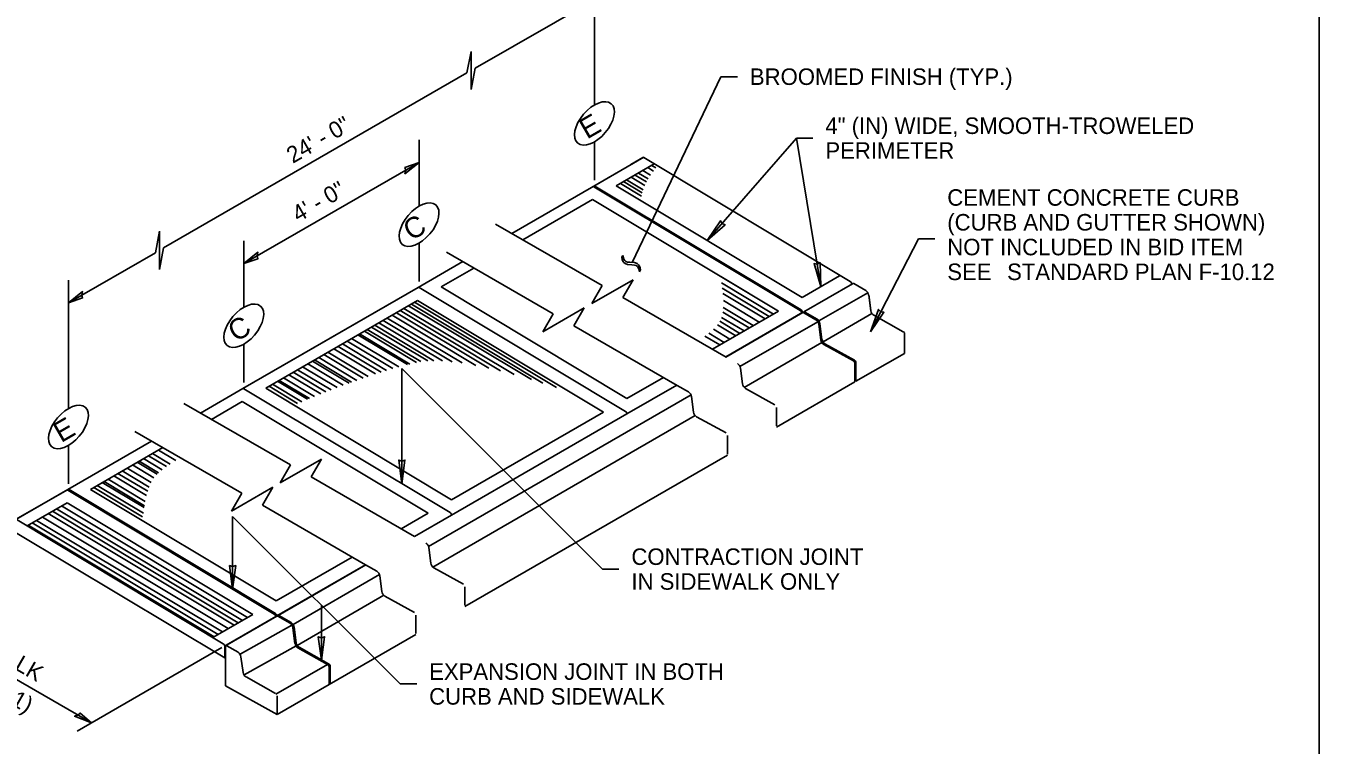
# Model space of a CAD drawing. Extents: x 99862 to 103151, y 100000 to 102076.
# Drawn here: x 101899 to 103151, y 100659 to 101355 of the extents above; entities that cross this region are included whole.
import ezdxf

# ---------------------------------------------------------------- set-up
doc = ezdxf.new("R2010")
doc.units = 0
for name, color, linetype in [('Level 1', 7, 'Continuous'), ('Level 15', 7, 'Continuous'), ('Level 20', 7, 'Continuous'), ('Level 27', 7, 'Continuous'), ('Level 30', 7, 'Continuous'), ('Level 4', 7, 'Continuous'), ('Level 7', 7, 'Continuous')]:
    doc.layers.add(name, color=color, linetype=linetype)

msp = doc.modelspace()

# ---------------------------------------------------------------- linework, layer by layer
at = {"layer": 'Level 1'}
msp.add_lwpolyline([(99862, 99999.5), (103151, 99999.5), (103151, 102075.5), (99862, 102075.5)], close=True, dxfattribs=at)
at = {"layer": 'Level 15'}
for p, q in [((102449.4, 101278.5), (102449.4, 101402.9)), ((102334, 101314.3), (102449.4, 101380.9)), ((102330, 101330.5), (102326, 101309.7)), ((102330, 101293.5), (102330, 101330.5)), ((102032.3, 101140.1), (102326, 101309.7)), ((102330, 101293.5), (102334, 101314.3)), ((102485.9, 101126.1), (102571.9, 101306)), ((102571.9, 101306), (102587.9, 101306)), ((102279.6, 101180.5), (102279.6, 101244.9)), ((102449.4, 101205.7), (102449.4, 101242.8)), ((102558.7, 101147.3), (102644.9, 101246.5)), ((102668.7, 101102.9), (102644.9, 101246.5)), ((102644.9, 101246.5), (102660.9, 101246.5)), ((102109.9, 101125), (102279.6, 101222.9)), ((102028.3, 101156.3), (102024.3, 101135.5)), ((102028.3, 101119.3), (102028.3, 101156.3)), ((102457, 101103.6), (102353.7, 101163.2)), ((102109.9, 101082.6), (102109.9, 101147)), ((102279.6, 101107.7), (102279.6, 101144.8)), ((102716.6, 101059), (102763, 101149)), ((102763, 101149), (102779, 101149)), ((101940.2, 101087), (102024.3, 101135.5)), ((102028.3, 101119.3), (102032.3, 101140.1)), ((102306.3, 101135.9), (102409.6, 101076.3)), ((101940.2, 100984.6), (101940.2, 101109)), ((102487, 101109.4), (102447, 101086.3)), ((102447, 101086.3), (102457, 101103.6)), ((102477, 101092.1), (102487, 101109.4)), ((102576.9, 101034.4), (102477, 101092.1)), ((102399.6, 101058.9), (102439.6, 101082)), ((102439.6, 101082), (102429.6, 101064.7)), ((102409.6, 101076.3), (102399.6, 101058.9)), ((102429.6, 101064.7), (102529.6, 101007)), ((102109.9, 101009.7), (102109.9, 101046.8)), ((102457.1, 100829.1), (102262.9, 101023.3)), ((102262.9, 100911.8), (102262.9, 101023.3)), ((102592.7, 101008.4), (102590.7, 101023.7)), ((102529.6, 101007), (102540.6, 101000.7)), ((102624.2, 100988.2), (102595.6, 101004.1)), ((102543.4, 100996.4), (102545.4, 100981.1)), ((102155.3, 100929.9), (102052, 100989.5)), ((102625.7, 100967.8), (102625.7, 100985.7)), ((102548.2, 100976.7), (102576.9, 100960.9)), ((102004.6, 100962.2), (102107.9, 100902.5)), ((102578.3, 100958.4), (102578.3, 100940.5)), ((101940.2, 100911.8), (101940.2, 100948.9)), ((102185.3, 100935.6), (102145.3, 100912.6)), ((102145.3, 100912.6), (102155.3, 100929.9)), ((102175.3, 100918.3), (102185.3, 100935.6)), ((102275.2, 100860.6), (102175.3, 100918.3)), ((102097.9, 100885.2), (102137.9, 100908.3)), ((102107.9, 100902.5), (102097.9, 100885.2)), ((102137.9, 100908.3), (102127.9, 100891)), ((102127.9, 100891), (102227.8, 100833.3)), ((102261.4, 100717.8), (102099.1, 100880.1)), ((102099.1, 100880.1), (102099.1, 100809.7)), ((102291, 100834.7), (102289, 100850)), ((102227.8, 100833.3), (102238.8, 100827)), ((102322.5, 100814.5), (102293.9, 100830.3)), ((102457.1, 100829.1), (102473.1, 100829.1)), ((102241.6, 100822.6), (102243.7, 100807.4)), ((102246.5, 100803), (102275.2, 100787.1)), ((102324, 100794.1), (102324, 100812)), ((101755.5, 100799.6), (101962.4, 100680.2)), ((102185.1, 100740.8), (102185.1, 100794.1)), ((102276.6, 100784.6), (102276.6, 100766.7)), ((101948.7, 100672.1), (102088.7, 100753.1)), ((102261.4, 100717.8), (102277.4, 100717.8))]:
    msp.add_line(p, q, dxfattribs=at)
for points in [[(102279.6, 101222.9), (102266, 101212), (102266.7, 101215.4), (102266, 101218.2)], [(102558.7, 101147.3), (102575.9, 101162.6), (102573, 101163.7), (102571.4, 101166.5)], [(102109.9, 101125), (102123.6, 101135.9), (102122.9, 101132.5), (102123.6, 101129.7)], [(102668.7, 101102.9), (102662, 101124.9), (102665.1, 101124.3), (102667.9, 101125.9)], [(101940.2, 101087), (101953.9, 101097.9), (101953.2, 101094.5), (101953.9, 101091.8)], [(102716.6, 101059), (102724.4, 101080.6), (102726.6, 101078.3), (102729.7, 101077.9)], [(102262.9, 100911.8), (102265.9, 100934.7), (102262.9, 100933.6), (102260, 100934.7)], [(102099.1, 100809.7), (102102.1, 100832.5), (102099.1, 100831.5), (102096.2, 100832.5)], [(102185.1, 100740.8), (102188.1, 100763.6), (102185.1, 100762.6), (102182.1, 100763.6)], [(101962.4, 100680.2), (101951.5, 100689.6), (101949.4, 100687.7), (101946.1, 100686.5)]]:
    msp.add_lwpolyline(points, close=True, dxfattribs=at)
for centre, start_param, end_param in [((102587.9, 101024.8), 0.950564, 2.35604), ((102595.5, 101007.4), 4.092139, 5.517494), ((102540.6, 100997.4), 0.950564, 2.35604), ((102548.2, 100980), 4.092139, 5.517494), ((102286.2, 100851), 0.950564, 2.35604), ((102293.8, 100833.6), 4.092139, 5.517494), ((102238.8, 100823.7), 0.950564, 2.35604), ((102246.5, 100806.3), 4.092139, 5.517494)]:
    msp.add_ellipse(centre, major_axis=(2, -3.46), ratio=0.57735, start_param=start_param, end_param=end_param, dxfattribs=at)
at = {"layer": 'Level 20'}
for p, q in [((102476.9, 101132.9), (102475.9, 101131.1)), ((102475.9, 101131.1), (102476.2, 101129)), ((102476.2, 101129), (102476.9, 101127.3)), ((102477.9, 101129.4), (102476.9, 101132.9)), ((102478.8, 101128), (102477.9, 101129.4)), ((102479.9, 101127.1), (102478.8, 101128)), ((102476.9, 101127.3), (102477.8, 101126)), ((102477.8, 101126), (102479.2, 101125)), ((102479.2, 101125), (102481.5, 101124.1)), ((102481.3, 101126.5), (102479.9, 101127.1)), ((102483.7, 101126.3), (102481.3, 101126.5)), ((102481.5, 101124.1), (102485.6, 101123.9)), ((102488.1, 101125.9), (102483.7, 101126.3)), ((102485.6, 101123.9), (102488.1, 101123.6)), ((102490.7, 101125), (102488.1, 101125.9)), ((102488.1, 101123.6), (102489.9, 101123)), ((102489.9, 101123), (102491, 101122.2)), ((102492, 101123.9), (102490.7, 101125)), ((102491, 101122.2), (102491.8, 101121.1)), ((102491.8, 101121.1), (102492.4, 101119.5)), ((102493.1, 101122.6), (102492, 101123.9)), ((102492.4, 101119.5), (102492.9, 101117.1)), ((102492.9, 101117.1), (102494, 101118.9)), ((102493.7, 101120.9), (102493.1, 101122.6)), ((102494, 101118.9), (102493.7, 101120.9))]:
    msp.add_line(p, q, dxfattribs=at)
for centre in [(102449.4, 101260.7), (102279.6, 101162.7), (102109.9, 101064.7), (101940.2, 100966.7)]:
    msp.add_ellipse(centre, major_axis=(-16.2, -19.1), ratio=0.550454, dxfattribs=at)
at = {"layer": 'Level 27'}
for p, q in [((102666.8, 101069.4), (102714.2, 101096.7)), ((102590.3, 101025.2), (102665.7, 101068.7)), ((102670.7, 101049.1), (102718.1, 101076.5)), ((102594.4, 101005.1), (102669.6, 101048.5)), ((102288.7, 100851.1), (102542.9, 100997.9)), ((102292.9, 100831), (102547, 100977.7)), ((102157.6, 100775.4), (102241.4, 100823.7)), ((102161.6, 100755.2), (102245.6, 100803.7)), ((102156.6, 100774.8), (102106.3, 100746.7)), ((102160.5, 100754.6), (102110.2, 100726.5))]:
    msp.add_line(p, q, dxfattribs=at)
at = {"layer": 'Level 30'}
for p, q in [((102506.6, 101214.6), (102501.1, 101217.9)), ((102509, 101217.6), (102504.9, 101220.1)), ((102495.6, 101193.6), (102477.7, 101204.4)), ((102496.5, 101196.3), (102480.4, 101206)), ((102498.1, 101200.6), (102484.9, 101208.6)), ((102499.8, 101204.1), (102488.7, 101210.7)), ((102501.5, 101207.1), (102492.1, 101212.7)), ((102503.7, 101210.6), (102496.3, 101215.1)), ((102494.9, 101190.4), (102474.6, 101202.6)), ((102571.9, 101112.4), (102627.5, 101079)), ((102572.5, 101106.3), (102622.7, 101076.1)), ((102573.1, 101101.1), (102618.6, 101073.8)), ((102573.7, 101096), (102614.6, 101071.5)), ((102261.2, 101079.4), (102358.3, 101021.1)), ((102265, 101081.6), (102371.6, 101017.6)), ((102269.4, 101084.2), (102388.5, 101012.7)), ((102272.2, 101085.8), (102399.6, 101009.3)), ((102275.3, 101087.5), (102412.7, 101005)), ((102573.6, 101077.9), (102599.2, 101062.6)), ((102574.1, 101082.4), (102603.2, 101064.9)), ((102574.2, 101089.1), (102608.9, 101068.2)), ((102236.7, 101065.3), (102293.9, 101030.9)), ((102240.8, 101067.7), (102302.3, 101030.7)), ((102245, 101070), (102311.7, 101029.9)), ((102248.8, 101072.2), (102321.2, 101028.7)), ((102253.6, 101075), (102334.5, 101026.4)), ((102257.7, 101077.4), (102347.1, 101023.8)), ((102568.6, 101065.6), (102586.2, 101055.1)), ((102570.9, 101069.1), (102590.3, 101057.4)), ((102572.4, 101072.9), (102594.3, 101059.8)), ((102220.4, 101055.9), (102268.3, 101027.1)), ((102222.1, 101056.9), (102270.7, 101027.7)), ((102226.7, 101059.5), (102277.2, 101029.2)), ((102229.5, 101061.1), (102281.3, 101030)), ((102233.6, 101063.5), (102288.2, 101030.7)), ((102556.4, 101054.8), (102570.8, 101046.2)), ((102560, 101057.5), (102574.9, 101048.5)), ((102564.6, 101061.4), (102580.5, 101051.8)), ((102197.1, 101042.4), (102237.5, 101018.1)), ((102201.2, 101044.8), (102242.8, 101019.8)), ((102205.4, 101047.2), (102248.1, 101021.5)), ((102210, 101049.8), (102254.1, 101023.3)), ((102214.3, 101052.3), (102259.9, 101025)), ((102171.9, 101027.8), (102206.3, 101007.1)), ((102176.4, 101030.5), (102211.8, 101009.2)), ((102178.4, 101031.6), (102214.2, 101010.1)), ((102182.6, 101034), (102219.4, 101011.9)), ((102187.4, 101036.8), (102225.4, 101014)), ((102191.3, 101039.1), (102230.2, 101015.7)), ((102153.7, 101017.3), (102184.6, 100998.8)), ((102157.8, 101019.7), (102189.5, 101000.7)), ((102161.9, 101022.1), (102194.4, 101002.6)), ((102166.8, 101024.9), (102200.2, 101004.8)), ((102134.4, 101006.2), (102162, 100989.6)), ((102137.8, 101008.2), (102166, 100991.2)), ((102142.6, 101011), (102171.7, 100993.6)), ((102144.3, 101011.9), (102173.6, 100994.3)), ((102148.4, 101014.3), (102178.3, 100996.3)), ((102021.6, 100941.1), (102038.7, 100930.8)), ((102027.4, 100944.4), (102044.3, 100934.3)), ((102002.2, 100929.9), (102023, 100917.4)), ((102006.7, 100932.5), (102026, 100920.9)), ((102008.7, 100933.6), (102027.4, 100922.3)), ((102012.9, 100936.1), (102030.8, 100925.3)), ((102017.7, 100938.8), (102035.1, 100928.4)), ((101978.7, 100916.3), (102014.6, 100894.7)), ((101984, 100919.3), (102015.8, 100900.3)), ((101988.1, 100921.8), (102016.9, 100904.5)), ((101992.2, 100924.1), (102018.3, 100908.5)), ((101997.1, 100926.9), (102020.3, 100913)), ((101964.7, 100908.2), (102012, 100879.8)), ((101968.1, 100910.2), (102012.7, 100883.4)), ((101972.9, 100913), (102013.5, 100888.6)), ((101974.6, 100913.9), (102013.8, 100890.4)), ((101933.6, 100890.2), (102113.5, 100782.2)), ((101914.9, 100879.5), (102094.9, 100771.4)), ((101920.6, 100882.8), (102100.6, 100774.7)), ((101924.7, 100885.1), (102104.6, 100777)), ((101928.7, 100887.4), (102108.7, 100779.4)), ((101901.1, 100871.5), (102081.1, 100763.5)), ((101905.2, 100873.9), (102085.2, 100765.8)), ((101909.3, 100876.2), (102089.2, 100768.2))]:
    msp.add_line(p, q, dxfattribs=at)
at = {"layer": 'Level 4'}
for p, q in [((102446.6, 101198.8), (102497.1, 101228)), ((102497.1, 101228), (102448.9, 101200.1)), ((102484.5, 101221.1), (102496.1, 101227.8)), ((102497.1, 101227.6), (102696.9, 101107.7)), ((102446.6, 101198.8), (102369.3, 101154.2)), ((102369.3, 101154.2), (102446.6, 101198.8)), ((102446.6, 101198.8), (102446.6, 101198.8)), ((102648.6, 101079.4), (102448.8, 101199.4)), ((102449.9, 101200), (102649.6, 101080.1)), ((102278.6, 101101.8), (102322, 101126.9)), ((102322, 101126.9), (102278.6, 101101.8)), ((102699.3, 101105.3), (102652.2, 101078.1)), ((102698.3, 101105.1), (102699.4, 101105.7)), ((102698.3, 101105.3), (102698.3, 101105.1)), ((102698.3, 101105.1), (102698.3, 101105.1)), ((102700.4, 101105.6), (102712.1, 101098.9)), ((102278.6, 101101.8), (102108.9, 101003.9)), ((102193.6, 101052.7), (102278.6, 101101.8)), ((102279.6, 101101.7), (102479.4, 100981.8)), ((102716.9, 101079.6), (102714.9, 101094.8)), ((102714.9, 101094.5), (102714.9, 101094.5)), ((102714.9, 101094.5), (102717, 101079.3)), ((102651, 101077.8), (102576.5, 101034.7)), ((102653.2, 101078), (102664.9, 101071.2)), ((102717, 101079.3), (102717, 101079.3)), ((102651.1, 101077.5), (102576.7, 101034.5)), ((102663.8, 101070.6), (102652.1, 101077.4)), ((102668.7, 101051), (102666.6, 101066.3)), ((102667.7, 101066.9), (102669.7, 101051.6)), ((102719.8, 101074.9), (102719.8, 101074.9)), ((102719.8, 101074.9), (102748.4, 101059)), ((102108.9, 101003.9), (102193.6, 101052.7)), ((102749.5, 101058), (102749.5, 101038)), ((102700.1, 101030.8), (102671.5, 101046.6)), ((102672.6, 101047.3), (102701.2, 101031.4)), ((102701.6, 101011.6), (102701.6, 101028.3)), ((102749.5, 101038), (102702.6, 101011)), ((102702.6, 101028.9), (102702.6, 101011)), ((102068, 100980.2), (102108.9, 101003.9)), ((102309.7, 100883.8), (102109.9, 101003.7)), ((102529.1, 101007.3), (102480.8, 100979.3)), ((102701.6, 101010.4), (102625.7, 100966.7)), ((102702.6, 101011), (102701.6, 101011.6)), ((102701.6, 101010.4), (102701.6, 101011.6)), ((102480.8, 100979.3), (102311.1, 100881.4)), ((101939.7, 100906.2), (102020.7, 100952.9)), ((102578.3, 100939.4), (102324, 100793)), ((101889.2, 100877), (101939.7, 100906.2)), ((101938.7, 100905.6), (101889.7, 100877.3)), ((102139.5, 100785.5), (101939.7, 100905.5)), ((101940.8, 100906.1), (102140.5, 100786.1)), ((102311.1, 100881.4), (102275.2, 100860.6)), ((101890.4, 100876.8), (102090.1, 100756.8)), ((102091.5, 100743), (101888.9, 100864.6)), ((102227.8, 100833.3), (102141.9, 100783.7)), ((102228, 100833.2), (102143.1, 100784.2)), ((102141.9, 100783.5), (102091.5, 100754.4)), ((102140.9, 100783.1), (102092.8, 100755.3)), ((102140.9, 100782.9), (102140.9, 100783.1)), ((102141.9, 100783.7), (102141.9, 100783.5)), ((102154.7, 100776.7), (102143, 100783.5)), ((102144, 100784.1), (102155.8, 100777.3)), ((102276.6, 100765.7), (102142.2, 100688.3)), ((102159.5, 100757.1), (102157.5, 100772.3)), ((102158.6, 100772.9), (102160.6, 100757.7)), ((102091.5, 100754.4), (102091.5, 100743)), ((102092.2, 100716), (102092.2, 100754)), ((102093.4, 100754.9), (102104.4, 100748.6)), ((102191, 100736.8), (102162.4, 100752.7)), ((102163.4, 100753.3), (102192.1, 100737.4)), ((102107.2, 100744.2), (102109.2, 100729)), ((102191, 100736.8), (102141, 100707.9)), ((102192.5, 100717.3), (102192.5, 100734.4)), ((102193.5, 100735), (102193.5, 100717.9)), ((102142.2, 100688.3), (102092.2, 100716)), ((102112.1, 100724.6), (102140.7, 100708.7)), ((102193.5, 100717.9), (102192.5, 100718.5)), ((102142.2, 100706.2), (102142.2, 100688.3))]:
    msp.add_line(p, q, dxfattribs=at)
for centre, major_axis, start_param, end_param in [((102497.1, 101226), (-1, 1.73), 5.478482, 6.263654), ((102696.9, 101106.1), (-1, 1.73), 3.927706, 5.47779), ((102700.4, 101104), (-1, 1.73), 5.499053, 6.283185), ((102279.6, 101100.1), (-1, 1.73), 5.47779, 6.283214), ((102279.6, 101100.1), (1, -1.73), 2.336197, 3.141593), ((102279.6, 101100.1), (1, -1.73), 3.125285, 3.141491), ((102712.1, 101095.6), (-2, 3.46), 4.092157, 5.497787), ((102648.6, 101077.8), (-1, 1.73), 4.010451, 5.47779), ((102649.6, 101078.4), (1, -1.73), 0.869364, 2.336197), ((102652.1, 101075.8), (-1, 1.73), 5.497787, 6.283202), ((102653.2, 101076.4), (1, -1.73), 2.356194, 3.700583), ((102719.8, 101078.2), (-2, 3.46), 0.950547, 2.376192), ((102663.8, 101067.3), (-2, 3.46), 4.092157, 5.497787), ((102664.9, 101068), (2, -3.46), 0.950564, 2.356194), ((102748.5, 101057.4), (-1, 1.73), 4.727378, 5.517796), ((102671.4, 101049.9), (-2, 3.46), 0.950547, 2.376192), ((102672.5, 101050.6), (2, -3.46), 4.092139, 5.517784), ((102700.2, 101029.1), (-1, 1.73), 4.930096, 5.517796), ((102700.2, 101029.1), (-1, 1.73), 3.926984, 4.930836), ((102701.2, 101029.7), (1, -1.73), 1.787425, 2.376203), ((102701.2, 101029.7), (1, -1.73), 0.785392, 1.788296), ((102109.9, 101002.1), (-1, 1.73), 5.47779, 6.283185), ((102109.9, 101002.1), (1, -1.73), 2.336197, 3.141593), ((102109.9, 101002.1), (1, -1.73), 3.127788, 3.140446), ((102479.4, 100980.2), (-1, 1.73), 3.926981, 5.47779), ((102479.4, 100980.2), (1, -1.73), 0.785388, 2.336197), ((101939.7, 100903.8), (-1, 1.73), 5.47779, 6.283219), ((101940.7, 100904.4), (1, -1.73), 2.336197, 3.152337), ((101940.7, 100904.4), (1, -1.73), 3.140368, 3.152337), ((102309.7, 100882.2), (-1, 1.73), 3.926981, 5.47779), ((102309.7, 100882.2), (1, -1.73), 0.785388, 2.336197), ((102139.4, 100783.9), (-1, 1.73), 3.926981, 5.47779), ((102140.5, 100784.5), (1, -1.73), 0.785388, 2.336197), ((102143, 100781.8), (-1, 1.73), 5.497787, 6.283202), ((102144, 100782.4), (1, -1.73), 2.356194, 3.700583), ((102155.8, 100774), (2, -3.46), 0.950564, 2.356194), ((102154.7, 100773.4), (-2, 3.46), 4.092157, 5.497787), ((102090.1, 100755.2), (1, -1.73), 0.785388, 2.336197), ((102093.6, 100753.2), (1, -1.73), 2.356194, 3.926988), ((102162.3, 100756), (-2, 3.46), 0.950547, 2.376192), ((102163.4, 100756.6), (2, -3.46), 4.092139, 5.517784), ((102104.4, 100745.3), (2, -3.46), 0.950564, 2.35604), ((102112, 100727.9), (2, -3.46), 4.092139, 5.517494), ((102191.1, 100735.2), (-1, 1.73), 4.726483, 5.517796), ((102191.1, 100735.2), (-1, 1.73), 3.926984, 4.726483), ((102192.1, 100735.8), (1, -1.73), 1.58489, 2.376203), ((102192.1, 100735.8), (1, -1.73), 0.785392, 1.58489)]:
    msp.add_ellipse(centre, major_axis=major_axis, ratio=0.57735, start_param=start_param, end_param=end_param, dxfattribs=at)
at = {"layer": 'Level 7'}
for p, q in [((102507.3, 101221.5), (102470.6, 101200.3)), ((102470.6, 101200.3), (102650.5, 101092.2)), ((102447.6, 101187), (102380.1, 101148)), ((102627.5, 101079), (102447.6, 101187)), ((102332.7, 101120.7), (102300.9, 101102.3)), ((102650.5, 101092.2), (102686.5, 101113)), ((102300.9, 101102.3), (102480.8, 100994.2)), ((102278.2, 101089.2), (102131.2, 101004.3)), ((102458.2, 100981.2), (102278.2, 101089.2)), ((102563.6, 101042.1), (102627.5, 101079)), ((102131.2, 101004.3), (102311.1, 100896.3)), ((102480.8, 100994.2), (102516.3, 101014.7)), ((102108.5, 100991.3), (102078.7, 100974.1)), ((102288.5, 100883.2), (102108.5, 100991.3)), ((102311.1, 100896.3), (102458.2, 100981.2)), ((102031.4, 100946.7), (101961.4, 100906.3)), ((101961.4, 100906.3), (102141.4, 100798.3)), ((101938.8, 100893.3), (101900.1, 100870.9)), ((102118.8, 100785.2), (101938.8, 100893.3)), ((102262.3, 100868.1), (102288.5, 100883.2)), ((102141.4, 100798.3), (102215, 100840.7)), ((102080.1, 100762.9), (102118.8, 100785.2))]:
    msp.add_line(p, q, dxfattribs=at)

# ---------------------------------------------------------------- texts
at = {"layer": 'Level 20'}
for s, p in [('BROOMED FINISH (TYP.)', (102599.9, 101298)), ('4" (IN) WIDE, SMOOTH-TROWELED', (102673, 101250.5)), ('PERIMETER', (102673, 101226.5)), ('CEMENT CONCRETE CURB', (102791, 101181)), ('(CURB AND GUTTER SHOWN)', (102791, 101157)), ('NOT INCLUDED IN BID ITEM', (102791, 101133)), ('SEE ', (102791, 101109)), ('STANDARD PLAN F-10.12', (102848.9, 101109)), ('CONTRACTION JOINT', (102485.2, 100833.1)), ('IN SIDEWALK ONLY', (102485.2, 100809.1)), ('EXPANSION JOINT IN BOTH', (102289.4, 100721.8)), ('CURB AND SIDEWALK', (102289.4, 100697.8))]:
    msp.add_text(s, height=16, dxfattribs=at).set_placement(p)
for s, height, rotation, p in [('24\' - 0"', 16, 30, (102157.3, 101221.5)), ('E', 20, 30, (102442.2, 101245)), ('4\' - 0"', 16, 30, (102162.7, 101164.6)), ('C', 20, 30, (102271.8, 101146.6)), ('C', 20, 30, (102102.1, 101048.6)), ('E', 20, 30, (101933.1, 100951)), ('SIDEWALK', 16, 330.0271, (101814, 100774.7)), ('(SEE NOTE 1)', 16, 330.0271, (101778.4, 100759))]:
    msp.add_text(s, height=height, rotation=rotation, dxfattribs=at).set_placement(p)

doc.saveas('drawing.dxf')
